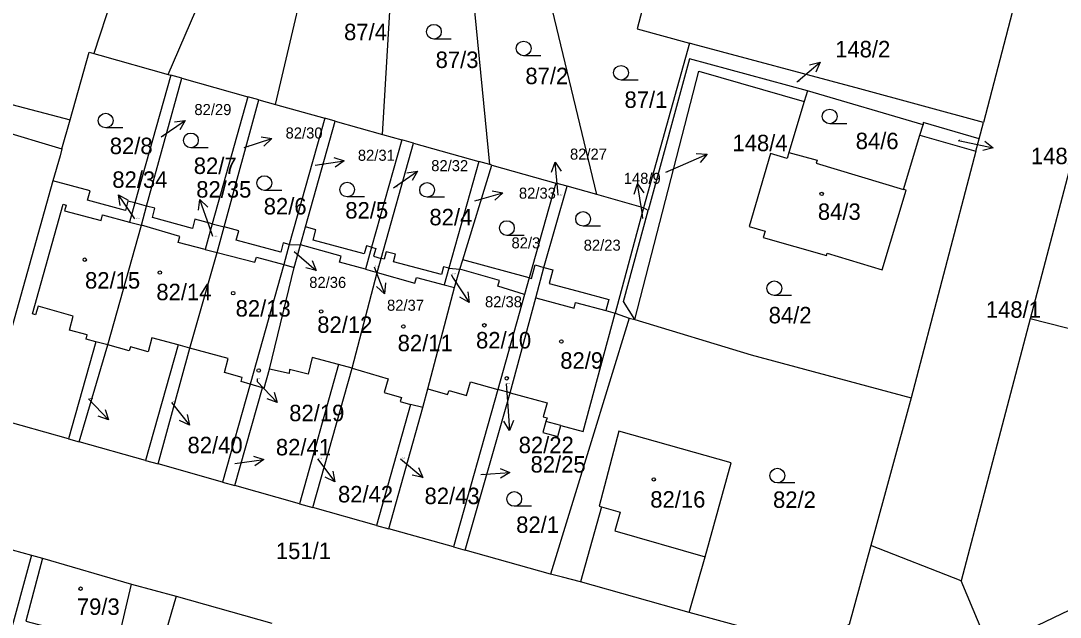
# Model space of a CAD drawing. Extents: x -737240 to -735272, y -1119606 to -1117878.
# Drawn here: x -736926.2 to -736818.9, y -1119123.6 to -1119062 of the extents above; entities that cross this region are included whole.
import ezdxf

# ---------------------------------------------------------------- set-up
doc = ezdxf.new("R2010")
doc.units = 0
for name, color, linetype in [('Level 1', 7, 'Continuous'), ('Level 16', 7, 'Continuous'), ('Level 18', 7, 'Continuous'), ('Level 19', 7, 'Continuous'), ('Level 25', 7, 'Continuous'), ('Level 4', 7, 'Continuous')]:
    doc.layers.add(name, color=color, linetype=linetype)

msp = doc.modelspace()

# ---------------------------------------------------------------- linework, layer by layer
at = {"layer": 'Level 1'}
for p, q in [((-736913.48, -1119049.57), (-736918.62, -1119065.38)), ((-736877.77, -1119076.84), (-736879.58, -1119058.32)), ((-736823.66, -1119060.36), (-736826.81, -1119072.48)), ((-736857.14, -1119064.31), (-736861.91, -1119081.3)), ((-736910.68, -1119067.6), (-736914.39, -1119080.79)), ((-736910.94, -1119067.53), (-736910.68, -1119067.6)), ((-736909.54, -1119067.92), (-736910.68, -1119067.6)), ((-736913.17, -1119081.12), (-736909.54, -1119067.92)), ((-736909.54, -1119067.92), (-736902.73, -1119069.83)), ((-736902.73, -1119069.83), (-736906.42, -1119082.95)), ((-736901.58, -1119070.15), (-736902.73, -1119069.83)), ((-736844.99, -1119069.22), (-736845.33, -1119070.34)), ((-736833.05, -1119072.74), (-736844.99, -1119069.22)), ((-736905.18, -1119083.28), (-736901.58, -1119070.15)), ((-736901.58, -1119070.15), (-736899.88, -1119070.63)), ((-736899.88, -1119070.63), (-736894.79, -1119072.06)), ((-736845.33, -1119070.34), (-736846.91, -1119075.58)), ((-736894.79, -1119072.06), (-736898.45, -1119085.1)), ((-736893.73, -1119072.36), (-736894.79, -1119072.06)), ((-736816.39, -1119071.39), (-736822, -1119092.75)), ((-736928.66, -1119073.19), (-736921.92, -1119075.23)), ((-736921.92, -1119075.23), (-736921.07, -1119072.21)), ((-736896.79, -1119083.28), (-736893.73, -1119072.36)), ((-736893.73, -1119072.36), (-736888.83, -1119073.74)), ((-736833.37, -1119073.8), (-736833.05, -1119072.74)), ((-736827.25, -1119074.17), (-736826.81, -1119072.48)), ((-736886.85, -1119074.29), (-736889.96, -1119085.38)), ((-736888.83, -1119073.74), (-736886.85, -1119074.29)), ((-736885.64, -1119074.63), (-736886.85, -1119074.29)), ((-736835.06, -1119079.41), (-736833.37, -1119073.8)), ((-736833.37, -1119073.8), (-736827.59, -1119075.47)), ((-736827.59, -1119075.47), (-736827.25, -1119074.17)), ((-736888.97, -1119086.53), (-736885.64, -1119074.63)), ((-736885.64, -1119074.63), (-736878.9, -1119076.52)), ((-736827.59, -1119075.47), (-736834.28, -1119100.93)), ((-736878.9, -1119076.52), (-736881.99, -1119087.54)), ((-736880.55, -1119086.68), (-736877.55, -1119076.9)), ((-736877.77, -1119076.84), (-736878.9, -1119076.52)), ((-736877.55, -1119076.9), (-736877.77, -1119076.84)), ((-736877.55, -1119076.9), (-736870.96, -1119078.75)), ((-736922.84, -1119078.51), (-736929.66, -1119102.79)), ((-736870.96, -1119078.75), (-736873.71, -1119088.54)), ((-736872.17, -1119087.45), (-736869.79, -1119079.08)), ((-736869.79, -1119079.08), (-736870.96, -1119078.75)), ((-736866.72, -1119079.94), (-736869.79, -1119079.08)), ((-736861.91, -1119081.3), (-736866.72, -1119079.94)), ((-736914.39, -1119080.79), (-736914.94, -1119082.77)), ((-736913.17, -1119081.12), (-736914.39, -1119080.79)), ((-736913.72, -1119083.1), (-736913.17, -1119081.12)), ((-736861.91, -1119081.3), (-736864.82, -1119092.17)), ((-736861.4, -1119081.57), (-736861.91, -1119081.3)), ((-736914.94, -1119082.77), (-736913.72, -1119083.1)), ((-736917.18, -1119095.46), (-736913.72, -1119083.1)), ((-736906.42, -1119082.95), (-736907.15, -1119085.59)), ((-736906.42, -1119082.95), (-736905.18, -1119083.28)), ((-736905.9, -1119085.92), (-736905.18, -1119083.28)), ((-736897.3, -1119085.12), (-736896.79, -1119083.28)), ((-736908.7, -1119095.79), (-736905.9, -1119085.92)), ((-736907.15, -1119085.59), (-736905.9, -1119085.92)), ((-736898.45, -1119085.1), (-736899.03, -1119087.16)), ((-736898.45, -1119085.1), (-736897.3, -1119085.12)), ((-736897.95, -1119087.45), (-736897.3, -1119085.12)), ((-736889.96, -1119085.38), (-736890.6, -1119087.64)), ((-736899.03, -1119087.16), (-736902.5, -1119099.51)), ((-736899.03, -1119087.16), (-736897.95, -1119087.45)), ((-736889.37, -1119087.97), (-736888.97, -1119086.53)), ((-736880.85, -1119087.65), (-736880.55, -1119086.68)), ((-736873.71, -1119088.54), (-736880.55, -1119086.68)), ((-736900.51, -1119097.96), (-736897.95, -1119087.45)), ((-736891.98, -1119097.86), (-736889.37, -1119087.97)), ((-736890.6, -1119087.64), (-736889.37, -1119087.97)), ((-736881.99, -1119087.54), (-736882.47, -1119089.24)), ((-736881.99, -1119087.54), (-736880.85, -1119087.65)), ((-736881.39, -1119089.53), (-736880.85, -1119087.65)), ((-736873.01, -1119090.58), (-736872.17, -1119087.45)), ((-736882.47, -1119089.24), (-736881.39, -1119089.53)), ((-736873.71, -1119088.54), (-736874.19, -1119090.26)), ((-736884.14, -1119100), (-736881.39, -1119089.53)), ((-736874.19, -1119090.26), (-736876.94, -1119100.05)), ((-736875.65, -1119100.4), (-736873.01, -1119090.58)), ((-736865.78, -1119091.91), (-736864.82, -1119092.17)), ((-736864.82, -1119092.17), (-736863.38, -1119092.71)), ((-736863.38, -1119092.71), (-736871.49, -1119119.13)), ((-736863.38, -1119092.71), (-736862.79, -1119092.83)), ((-736822, -1119092.75), (-736829.11, -1119119.8)), ((-736796.29, -1119099.44), (-736822, -1119092.75)), ((-736918.41, -1119095.14), (-736921.23, -1119105.15)), ((-736920.14, -1119105.46), (-736917.18, -1119095.46)), ((-736917.18, -1119095.46), (-736918.41, -1119095.14)), ((-736909.93, -1119095.46), (-736913.28, -1119107.38)), ((-736908.7, -1119095.79), (-736909.93, -1119095.46)), ((-736911.99, -1119107.74), (-736908.7, -1119095.79)), ((-736893.36, -1119097.49), (-736897.39, -1119111.85)), ((-736896.01, -1119112.24), (-736891.98, -1119097.86)), ((-736891.98, -1119097.86), (-736893.36, -1119097.49)), ((-736902.5, -1119099.51), (-736905.34, -1119109.62)), ((-736904.08, -1119109.97), (-736901.22, -1119099.88)), ((-736901.22, -1119099.88), (-736902.5, -1119099.51)), ((-736884.67, -1119101.93), (-736884.14, -1119100)), ((-736876.94, -1119100.05), (-736881.5, -1119116.31)), ((-736880.29, -1119116.65), (-736875.65, -1119100.4)), ((-736875.65, -1119100.4), (-736876.94, -1119100.05)), ((-736834.28, -1119100.93), (-736838.44, -1119116.17)), ((-736885.93, -1119101.59), (-736889.44, -1119114.08)), ((-736888.19, -1119114.43), (-736884.67, -1119101.93)), ((-736884.67, -1119101.93), (-736885.93, -1119101.59)), ((-736921.23, -1119105.15), (-736929.66, -1119102.79)), ((-736921.23, -1119105.15), (-736920.14, -1119105.46)), ((-736913.28, -1119107.38), (-736920.14, -1119105.46)), ((-736913.28, -1119107.38), (-736911.99, -1119107.74)), ((-736905.34, -1119109.62), (-736911.99, -1119107.74)), ((-736905.34, -1119109.62), (-736904.08, -1119109.97)), ((-736897.39, -1119111.85), (-736904.08, -1119109.97)), ((-736897.39, -1119111.85), (-736896.01, -1119112.24)), ((-736889.44, -1119114.08), (-736896.01, -1119112.24)), ((-736866.22, -1119112.18), (-736868.39, -1119119.91)), ((-736889.44, -1119114.08), (-736888.19, -1119114.43)), ((-736881.5, -1119116.31), (-736888.19, -1119114.43)), ((-736925.04, -1119117.17), (-736927.6, -1119126.54)), ((-736927.06, -1119116.6), (-736925.04, -1119117.17)), ((-736925.04, -1119117.17), (-736923.93, -1119117.48)), ((-736881.5, -1119116.31), (-736880.29, -1119116.65)), ((-736871.49, -1119119.13), (-736880.29, -1119116.65)), ((-736829.11, -1119119.8), (-736838.44, -1119116.17)), ((-736923.93, -1119117.48), (-736914.72, -1119120.16)), ((-736857.18, -1119123.06), (-736855.55, -1119117.34)), ((-736914.72, -1119120.16), (-736910.14, -1119121.39)), ((-736857.18, -1119123.06), (-736868.39, -1119119.91)), ((-736910.14, -1119121.39), (-736912.85, -1119130.67)), ((-736910.14, -1119121.39), (-736900.24, -1119124.19))]:
    msp.add_line(p, q, dxfattribs=at)
for points in [[(-736899.88, -1119070.63), (-736895.51, -1119052.04), (-736893.96, -1119047.52)], [(-736910.94, -1119067.53), (-736903.37, -1119050), (-736903.23, -1119049.72)], [(-736888.83, -1119073.74), (-736887.65, -1119054.08), (-736887.05, -1119053.28)], [(-736860.93, -1119056.62), (-736862.54, -1119062.84), (-736857.14, -1119064.31)], [(-736866.72, -1119079.94), (-736871.93, -1119058.16), (-736871.37, -1119057.65)], [(-736826.81, -1119072.48), (-736839.56, -1119069.02), (-736856.8, -1119064.4), (-736857.14, -1119064.31)], [(-736921.07, -1119072.21), (-736919.11, -1119065.24), (-736918.62, -1119065.38)], [(-736918.62, -1119065.38), (-736918.01, -1119065.55), (-736910.94, -1119067.53)], [(-736844.99, -1119069.22), (-736857.16, -1119065.92), (-736861.4, -1119081.57)], [(-736862.79, -1119092.83), (-736856.18, -1119067.21), (-736845.33, -1119070.34)], [(-736827.25, -1119074.17), (-736833.03, -1119072.48), (-736833.05, -1119072.74)], [(-736921.92, -1119075.23), (-736922.11, -1119075.92), (-736922.84, -1119078.51)], [(-736846.91, -1119075.58), (-736847.08, -1119076.21), (-736848.78, -1119075.71), (-736851.01, -1119083.24), (-736849.34, -1119083.7), (-736849.55, -1119084.38), (-736843.03, -1119086.21), (-736842.96, -1119085.98), (-736837.27, -1119087.7), (-736834.79, -1119079.49), (-736835.06, -1119079.41)], [(-736846.91, -1119075.58), (-736843.99, -1119076.37), (-736844.08, -1119076.68), (-736835.06, -1119079.41)], [(-736914.39, -1119080.79), (-736915.1, -1119080.6), (-736915.35, -1119081.57), (-736919.27, -1119080.51), (-736919.01, -1119079.55), (-736922.84, -1119078.51)], [(-736906.42, -1119082.95), (-736908.19, -1119082.47), (-736908.45, -1119083.43), (-736912.58, -1119082.31), (-736912.32, -1119081.35), (-736913.17, -1119081.12)], [(-736862.79, -1119092.83), (-736863.95, -1119090.98), (-736861.4, -1119081.57)], [(-736898.45, -1119085.1), (-736899.08, -1119084.93), (-736899.34, -1119085.89), (-736903.93, -1119084.65), (-736903.67, -1119083.69), (-736905.18, -1119083.28)], [(-736889.96, -1119085.38), (-736890.5, -1119085.24), (-736890.72, -1119086.05), (-736895.99, -1119084.63), (-736895.7, -1119083.57), (-736896.79, -1119083.28)], [(-736889.96, -1119085.38), (-736889.53, -1119085.5), (-736889.76, -1119086.31), (-736888.97, -1119086.53)], [(-736881.99, -1119087.54), (-736882.53, -1119087.39), (-736882.76, -1119088.2), (-736887.71, -1119086.87), (-736887.5, -1119086.1), (-736888.46, -1119085.84), (-736888.67, -1119086.61), (-736888.97, -1119086.53)], [(-736873.71, -1119088.54), (-736873.47, -1119088.6), (-736873.09, -1119087.2), (-736872.17, -1119087.45)], [(-736872.17, -1119087.45), (-736871.25, -1119087.7), (-736871.62, -1119089.1), (-736868.26, -1119090), (-736865.47, -1119090.76), (-736865.78, -1119091.91)], [(-736870.42, -1119103.77), (-736868.11, -1119104.39), (-736864.82, -1119092.17)], [(-736862.79, -1119092.83), (-736850.79, -1119096.47), (-736834.28, -1119100.93)], [(-736901.22, -1119099.88), (-736901.03, -1119099.93), (-736900.51, -1119097.96)], [(-736875.65, -1119100.4), (-736871.85, -1119101.42), (-736872.24, -1119102.87), (-736871.85, -1119102.97), (-736871.96, -1119103.36)], [(-736871.96, -1119103.36), (-736872.27, -1119104.51), (-736870.73, -1119104.92), (-736870.42, -1119103.77)], [(-736855.55, -1119117.34), (-736852.84, -1119107.62), (-736864.44, -1119104.36), (-736866.46, -1119112.11), (-736866.22, -1119112.18)], [(-736838.44, -1119116.17), (-736840.67, -1119124.32), (-736843.82, -1119126.71), (-736857.18, -1119123.06)], [(-736923.93, -1119117.48), (-736925.63, -1119123.96), (-736916.21, -1119126.44), (-736914.72, -1119120.16)], [(-736868.39, -1119119.91), (-736870.27, -1119119.44), (-736871.49, -1119119.13)], [(-736814.71, -1119121.3), (-736826.19, -1119126.79), (-736829.11, -1119119.8)]]:
    msp.add_lwpolyline(points, dxfattribs=at)
at = {"layer": 'Level 16'}
for p, q in [((-736911.69, -1119073.96), (-736909.191, -1119072.3)), ((-736903.12, -1119075.06), (-736900.26, -1119074.153)), ((-736895.77, -1119076.9), (-736892.803, -1119076.457)), ((-736887.69, -1119079.23), (-736885.227, -1119077.518)), ((-736914.39, -1119082.44), (-736916.063, -1119079.95)), ((-736879.3, -1119080.57), (-736876.408, -1119079.773)), ((-736897.94, -1119085.81), (-736895.666, -1119087.766)), ((-736889.7, -1119087.38), (-736888.61, -1119090.175)), ((-736919.18, -1119101.03), (-736917.106, -1119103.198)), ((-736910.61, -1119101.39), (-736908.755, -1119103.748)), ((-736904.06, -1119107.7), (-736901.088, -1119107.288)), ((-736895.55, -1119107.21), (-736893.736, -1119109.599)), ((-736886.97, -1119107.21), (-736884.679, -1119109.146)), ((-736878.67, -1119108.83), (-736875.676, -1119108.636))]:
    msp.add_line(p, q, dxfattribs=at)
for points in [[(-736846.08, -1119068.32), (-736845.95, -1119068.21), (-736843.673, -1119066.257)], [(-736844.757, -1119066.528), (-736843.673, -1119066.257), (-736844.106, -1119067.287)], [(-736910.301, -1119072.437), (-736909.191, -1119072.3), (-736909.747, -1119073.27)], [(-736901.365, -1119073.979), (-736900.26, -1119074.153), (-736901.062, -1119074.932)], [(-736829.42, -1119074.35), (-736828.74, -1119074.49), (-736825.807, -1119075.119)], [(-736826.68, -1119074.42), (-736825.807, -1119075.119), (-736826.889, -1119075.398)], [(-736893.866, -1119076.11), (-736892.803, -1119076.457), (-736893.718, -1119077.099)], [(-736859.6, -1119077.64), (-736858.09, -1119076.97), (-736855.344, -1119075.762)], [(-736856.46, -1119075.707), (-736855.344, -1119075.762), (-736856.058, -1119076.623)], [(-736886.333, -1119077.678), (-736885.227, -1119077.518), (-736885.762, -1119078.499)], [(-736871.406, -1119077.622), (-736870.997, -1119076.582), (-736870.41, -1119077.533)], [(-736870.69, -1119080), (-736870.73, -1119079.57), (-736870.997, -1119076.582)], [(-736877.505, -1119079.557), (-736876.408, -1119079.773), (-736877.239, -1119080.521)], [(-736862.85, -1119079.9), (-736862.509, -1119078.835), (-736861.862, -1119079.747)], [(-736861.95, -1119082.42), (-736862.05, -1119081.8), (-736862.509, -1119078.835)], [(-736915.92, -1119081.059), (-736916.063, -1119079.95), (-736915.09, -1119080.501)], [(-736907.816, -1119081.56), (-736907.676, -1119080.45), (-736906.873, -1119081.227)], [(-736906.33, -1119084.27), (-736906.68, -1119083.28), (-736907.676, -1119080.45)], [(-736896.098, -1119086.735), (-736895.666, -1119087.766), (-736896.75, -1119087.493)], [(-736881.75, -1119088.18), (-736881.53, -1119088.57), (-736879.905, -1119091.092)], [(-736888.508, -1119089.062), (-736888.61, -1119090.175), (-736889.439, -1119089.425)], [(-736880.026, -1119089.98), (-736879.905, -1119091.092), (-736880.867, -1119090.522)], [(-736901.78, -1119098.96), (-736901.76, -1119099.22), (-736899.689, -1119101.39)], [(-736876.06, -1119099.48), (-736875.94, -1119101.28), (-736875.741, -1119104.273)], [(-736900.017, -1119100.321), (-736899.689, -1119101.39), (-736900.741, -1119101.012)], [(-736917.436, -1119102.13), (-736917.106, -1119103.198), (-736918.159, -1119102.821)], [(-736908.98, -1119102.653), (-736908.755, -1119103.748), (-736909.766, -1119103.271)], [(-736875.308, -1119103.242), (-736875.741, -1119104.273), (-736876.306, -1119103.309)], [(-736902.148, -1119106.93), (-736901.088, -1119107.288), (-736902.01, -1119107.92)], [(-736893.942, -1119108.5), (-736893.736, -1119109.599), (-736894.739, -1119109.105)], [(-736885.12, -1119108.119), (-736884.679, -1119109.146), (-736885.765, -1119108.883)], [(-736876.706, -1119108.202), (-736875.676, -1119108.636), (-736876.642, -1119109.2)]]:
    msp.add_lwpolyline(points, dxfattribs=at)
at = {"layer": 'Level 25'}
for p, q in [((-736881.748, -1119063.88), (-736883.53, -1119063.88)), ((-736872.488, -1119065.61), (-736874.27, -1119065.61)), ((-736862.438, -1119068.12), (-736864.22, -1119068.12)), ((-736915.618, -1119073.05), (-736917.4, -1119073.05)), ((-736840.898, -1119072.63), (-736842.68, -1119072.63)), ((-736906.828, -1119075.1), (-736908.61, -1119075.1)), ((-736899.238, -1119079.5), (-736901.02, -1119079.5)), ((-736890.698, -1119080.17), (-736892.48, -1119080.17)), ((-736882.448, -1119080.21), (-736884.23, -1119080.21)), ((-736866.348, -1119083.2), (-736868.13, -1119083.2)), ((-736874.218, -1119084.15), (-736876, -1119084.15)), ((-736846.618, -1119090.36), (-736848.4, -1119090.36)), ((-736846.298, -1119109.7), (-736848.08, -1119109.7)), ((-736873.458, -1119112.11), (-736875.24, -1119112.11))]:
    msp.add_line(p, q, dxfattribs=at)
for centre, major_axis, ratio in [((-736883.53, -1119063.124), (0.764, 0), 0.9894236), ((-736874.27, -1119064.854), (0.764, 0), 0.9894236), ((-736864.22, -1119067.364), (0.764, 0), 0.9894236), ((-736917.4, -1119072.294), (0.764, 0), 0.9894236), ((-736842.68, -1119071.874), (0.764, 0), 0.9894236), ((-736908.61, -1119074.344), (0.764, 0), 0.9894236), ((-736901.02, -1119078.744), (0.764, 0), 0.9894236), ((-736892.48, -1119079.414), (0.764, 0), 0.9894236), ((-736884.23, -1119079.454), (0.764, 0), 0.9894236), ((-736843.51, -1119079.87), (0.18, 0), 0.9848078), ((-736868.13, -1119082.444), (0.764, 0), 0.9894236), ((-736876, -1119083.394), (0.764, 0), 0.9894236), ((-736919.56, -1119086.66), (0.18, 0), 0.9848078), ((-736911.81, -1119087.99), (0.18, 0), 0.9848078), ((-736848.4, -1119089.604), (0.764, 0), 0.9894236), ((-736904.24, -1119090.11), (0.18, 0), 0.9848078), ((-736895.16, -1119092), (0.18, 0), 0.9848078), ((-736886.68, -1119093.55), (0.18, 0), 0.9848078), ((-736878.32, -1119093.43), (0.18, 0), 0.9848078), ((-736870.37, -1119095.1), (0.18, 0), 0.9848078), ((-736901.61, -1119098.1), (0.18, 0), 0.9848078), ((-736876.01, -1119098.9), (0.18, 0), 0.9848078), ((-736848.08, -1119108.944), (0.764, 0), 0.9894236), ((-736860.84, -1119109.34), (0.18, 0), 0.9848078), ((-736875.24, -1119111.354), (0.764, 0), 0.9894236), ((-736919.99, -1119120.62), (0.18, 0), 0.9848078)]:
    msp.add_ellipse(centre, major_axis=major_axis, ratio=ratio, dxfattribs=at)
at = {"layer": 'Level 4'}
msp.add_line((-736870.42, -1119103.77), (-736871.96, -1119103.36), dxfattribs=at)
for points in [[(-736928.66, -1119073.19), (-736927.73, -1119070.46), (-736921.07, -1119072.21)], [(-736918.41, -1119095.14), (-736919.42, -1119094.87), (-736919.3, -1119094.43), (-736921.13, -1119093.93), (-736920.74, -1119092.49), (-736924.38, -1119091.46), (-736924.63, -1119092.35), (-736924.94, -1119092.26), (-736921.78, -1119080.94), (-736921.48, -1119081.02), (-736921.64, -1119081.6), (-736917.88, -1119082.61), (-736917.72, -1119082.03), (-736914.94, -1119082.77)], [(-736907.15, -1119085.59), (-736909.92, -1119084.87), (-736909.74, -1119084.25), (-736913.72, -1119083.1)], [(-736905.9, -1119085.92), (-736902, -1119086.93), (-736901.85, -1119086.39), (-736899.03, -1119087.16)], [(-736890.6, -1119087.64), (-736893.27, -1119086.92), (-736893.09, -1119086.3), (-736897.3, -1119085.12)], [(-736889.37, -1119087.97), (-736885.48, -1119089.09), (-736885.32, -1119088.48), (-736882.47, -1119089.24)], [(-736874.19, -1119090.26), (-736876.92, -1119089.39), (-736876.76, -1119088.82), (-736880.85, -1119087.65)], [(-736873.01, -1119090.58), (-736869.06, -1119091.65), (-736868.91, -1119091.07), (-736865.78, -1119091.91)], [(-736909.93, -1119095.46), (-736912.62, -1119094.73), (-736913.03, -1119096.17), (-736914.85, -1119095.65), (-736914.97, -1119096.07), (-736917.18, -1119095.46)], [(-736902.5, -1119099.51), (-736903.43, -1119099.24), (-736903.32, -1119098.81), (-736905.15, -1119098.3), (-736904.75, -1119096.85), (-736908.7, -1119095.79)], [(-736893.36, -1119097.49), (-736896.09, -1119096.76), (-736896.51, -1119098.46), (-736898.43, -1119097.99), (-736898.48, -1119098.41), (-736900.51, -1119097.96)], [(-736891.98, -1119097.86), (-736888.26, -1119098.96), (-736888.65, -1119100.37), (-736886.86, -1119100.87), (-736887.01, -1119101.31), (-736885.93, -1119101.59)], [(-736884.14, -1119100), (-736882.12, -1119100.57), (-736881.97, -1119100.15), (-736880.17, -1119100.69), (-736879.74, -1119099.25), (-736876.94, -1119100.05)], [(-736866.22, -1119112.18), (-736864.31, -1119112.72), (-736864.86, -1119114.65), (-736855.55, -1119117.34)]]:
    msp.add_lwpolyline(points, dxfattribs=at)

# ---------------------------------------------------------------- texts
at = {"layer": 'Level 16'}
for s, height, p in [('148/2', 1.7, (-736842.12, -1119065.77)), ('82/29', 1.14, (-736908.245, -1119071.73)), ('82/30', 1.14, (-736898.835, -1119074.15)), ('148/4', 1.7, (-736852.72, -1119075.46)), ('82/31', 1.14, (-736891.375, -1119076.45)), ('82/27', 1.14, (-736869.485, -1119076.33)), ('148/5', 1.7, (-736821.92, -1119076.8)), ('82/32', 1.14, (-736883.805, -1119077.52)), ('82/34', 1.7, (-736916.715, -1119079.24)), ('82/35', 1.7, (-736908.055, -1119080.25)), ('148/9', 1.14, (-736863.935, -1119078.83)), ('82/33', 1.14, (-736874.755, -1119080.36)), ('82/36', 1.14, (-736896.395, -1119089.57)), ('82/38', 1.14, (-736878.255, -1119091.57)), ('82/37', 1.14, (-736888.365, -1119091.93)), ('82/19', 1.7, (-736898.46, -1119103.33)), ('82/40', 1.7, (-736908.955, -1119106.64)), ('82/41', 1.7, (-736899.835, -1119106.86)), ('82/22', 1.7, (-736874.78, -1119106.63)), ('82/25', 1.7, (-736873.555, -1119108.63)), ('82/42', 1.7, (-736893.425, -1119111.71)), ('82/43', 1.7, (-736884.495, -1119111.89))]:
    msp.add_text(s, height=height, dxfattribs=at).set_placement(p)
at = {"layer": 'Level 18'}
for s, height, p in [('87/4', 1.7, (-736892.8, -1119064)), ('87/3', 1.7, (-736883.35, -1119066.87)), ('87/2', 1.7, (-736874.09, -1119068.54)), ('148/2', 0.1, (-736846.08, -1119068.32)), ('87/1', 1.7, (-736863.86, -1119070.99)), ('82/8', 1.7, (-736916.98, -1119075.76)), ('82/29', 0.1, (-736911.565, -1119073.96)), ('84/6', 1.7, (-736840, -1119075.25)), ('148/5', 0.1, (-736829.42, -1119074.35)), ('82/30', 0.1, (-736902.995, -1119075.06)), ('82/7', 1.7, (-736908.31, -1119077.81)), ('82/31', 0.1, (-736895.645, -1119076.9)), ('148/4', 0.1, (-736859.6, -1119077.64)), ('82/32', 0.1, (-736887.565, -1119079.23)), ('82/6', 1.7, (-736901.09, -1119081.99)), ('82/5', 1.7, (-736892.67, -1119082.41)), ('82/33', 0.1, (-736879.175, -1119080.57)), ('82/27', 0.1, (-736870.565, -1119080)), ('82/4', 1.7, (-736883.99, -1119083.11)), ('82/34', 0.1, (-736914.265, -1119082.44)), ('148/9', 0.1, (-736861.825, -1119082.42)), ('82/35', 0.1, (-736906.205, -1119084.27)), ('82/3', 1.14, (-736875.52, -1119085.49)), ('82/23', 1.14, (-736868.07, -1119085.73)), ('82/36', 0.1, (-736897.815, -1119085.81)), ('82/37', 0.1, (-736889.575, -1119087.38)), ('82/38', 0.1, (-736881.625, -1119088.18)), ('84/2', 1.7, (-736848.98, -1119093.23)), ('148/1', 1.7, (-736826.57, -1119092.65)), ('82/39', 0.1, (-736919.055, -1119101.03)), ('82/40', 0.1, (-736910.485, -1119101.39)), ('82/42', 0.1, (-736895.425, -1119107.21)), ('82/43', 0.1, (-736886.845, -1119107.21)), ('82/41', 0.1, (-736903.935, -1119107.7)), ('82/25', 0.1, (-736878.545, -1119108.83)), ('82/2', 1.7, (-736848.53, -1119112.28)), ('82/1', 1.7, (-736875.04, -1119114.86)), ('151/1', 1.7, (-736899.835, -1119117.56))]:
    msp.add_text(s, height=height, dxfattribs=at).set_placement(p)
at = {"layer": 'Level 19'}
for s, height, p in [('84/3', 1.7, (-736843.905, -1119082.55)), ('82/15', 1.7, (-736919.53, -1119089.64)), ('82/14', 1.7, (-736912.17, -1119090.84)), ('82/13', 1.7, (-736903.99, -1119092.53)), ('82/12', 1.7, (-736895.57, -1119094.21)), ('82/11', 1.7, (-736887.27, -1119096.11)), ('82/10', 1.7, (-736879.18, -1119095.82)), ('82/9', 1.7, (-736870.49, -1119097.91)), ('82/19', 0.1, (-736901.78, -1119098.96)), ('82/22', 0.1, (-736876.06, -1119099.48)), ('82/16', 1.7, (-736861.2, -1119112.25)), ('79/3', 1.7, (-736920.375, -1119123.32))]:
    msp.add_text(s, height=height, dxfattribs=at).set_placement(p)

doc.saveas('drawing.dxf')
